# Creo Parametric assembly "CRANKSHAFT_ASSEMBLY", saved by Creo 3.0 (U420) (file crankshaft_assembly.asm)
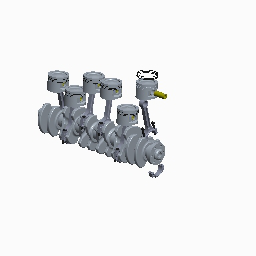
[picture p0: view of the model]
Units: millimeter Kilogram Sec (mmKs); MM, KILOGRAM, SECS

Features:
  1. datum plane "ASM_RIGHT"
  2. datum plane "ASM_TOP"
  3. datum plane "ASM_FRONT"
  4. coordinate system
  5. pattern
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
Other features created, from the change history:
  component "CONNECTING_ROD_ASSEMBLY" (3 times)
  planar section "A" (2 times)

Other components: CRANKSHAFT, PISTON_ASSEMBLY, PISTON_ASSEMBLY, PISTON_ASSEMBLY, PISTON_ASSEMBLY, PISTON_ASSEMBLY, PISTON_ASSEMBLY, CONNECTING_ROD_ASSEMBLY, CONNECTING_ROD_ASSEMBLY, CONNECTING_ROD_ASSEMBLY

Other named items: EXPLODED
